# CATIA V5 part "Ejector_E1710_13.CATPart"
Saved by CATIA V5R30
Part number: Vyhazovac_4x160_1
Nomenclature: E1710/4x160
Description: MEUSBURGER
Property "Material": "1.221"
Publications: "__DrillHole", "Base"
Bounding box of the stored display mesh (mm): x -3.996 to 3.996, y -3.999 to 3.999, z 0 to 152
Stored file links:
  E:\Bakalarka\Model\Forma_v7\Ejector_E1710_13.CATPart
  E:\dev\MoldDesign\intel_a\startup\components\MoldCatalog\Ejector\Meusburger\Ejector_E1710\TableE1710.txt
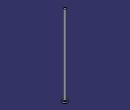
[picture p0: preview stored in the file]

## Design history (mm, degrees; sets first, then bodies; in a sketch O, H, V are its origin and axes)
Parameters
  Ref = "E1710/4x160" {design table}
  D1 = 4 mm {design table}
  D3 = 8 mm {design table}
  L = 160 mm {design table}
  L3 = 3 mm {design table}
  R = 0.3 mm {design table}
  k_d3 = 9 mm {design table}
  k_d1 = 4.2 mm {design table}
  k_F = 0.3 mm {design table}
  kl = 17 mm {design table}
  Mat = "1.221" {design table}
  HeatTreat = "ISO6751" {design table}
  Offset_Parting = 10 mm
  Anti_Rotation = "Normal"
  Anti_Rotation_D = 2.3 mm
  Anti_Rotation_D_Icut = 2.3 mm
  Add_Length_L = 0.8377 mm
  Add_Length_D3 = 0 mm
  SupplierRef = "Meusburger 2017"
  BmpRef = "F_MldEjectorD1"
  DrillHole_Length = 225 mm
  ValidationTest = false
  Anti_Rotation_D_min = 2.3 mm {= OffSet_D1 /2}
  Anti_Rotation_D_max = 3.925 mm {= D3/2-0.075mm}
  Anti_Rotation_D_ref = 2.3 mm {= Anti_Rotation_D}
  Anti_Rotation_D_Icut_ref = 2.3 mm {= Anti_Rotation_D_Icut}
  Anti_Rotation_Ref_Icut = 2.3246 mm
  Offset_L = 20 mm
  D = 4 mm {= D1}
  OffSet_D1 = 4.6 mm {= D1+2*R}
  OffSet_D3 = 9 mm {= D3+1mm}
  XG_Split = -159.5 mm
  YG_Split = 0 mm
  ZG_Split = -198 mm
  DirX_Split = 0 mm
  DirY_Split = 0 mm
  DirZ_Split = 1 mm
Set1 "BaseBody"
  Point1 "Base": (0, 0, 0)
  Plane1: type Offset, RefPlane xy-plane, Offset 225 {= DrillHole_Length}, reversed
  Sketch1 "Sketch.2" on xy-plane, origin (0, 0, 0), H (1, 0, 0), V (0, 1, 0)
    point P1 (-0.46, 1.1623)
    point P2 (0.46, 1.1623)
    construction line L1 (-0.46, 1.1623) -> (0.46, 1.1623)
    point P3 (0.46, -1.1623)
    line L2 (0.46, -1.1623) -> (0.46, 1.1623)
    point P4 (-0.46, -1.1623)
    construction line L3 (0.46, -1.1623) -> (-0.46, -1.1623)
    line L4 (-0.46, 1.1623) -> (-0.46, -1.1623)
    point P5 (-0.21, 1.1623)
    arc A1 centre (-0.21, 1.1623) radius 0.25 from (-0.21, 1.4123) to (-0.46, 1.1623) ccw
    point P7 (0.21, 1.1623)
    point P8 (0.21, 1.4123)
    arc A2 centre (0.21, 1.1623) radius 0.25 from (0.46, 1.1623) to (0.21, 1.4123) ccw
    line L5 (-0.21, 1.4123) -> (0.21, 1.4123)
    point P9 (-0.46, -1.1623)
    arc A3 centre (-0.21, -1.1623) radius 0.25 from (-0.46, -1.1623) to (-0.21, -1.4123) ccw
    point P11 (0.21, -1.4123)
    line L6 (-0.21, -1.4123) -> (0.21, -1.4123)
    point P12 (0.46, -1.1623)
    arc A4 centre (0.21, -1.1623) radius 0.25 from (0.21, -1.4123) to (0.46, -1.1623) ccw
    point P14 (-0.46, 1.1623)
    point P15 (-0.46, -1.1623)
    point P16 (0.46, 1.1623)
    point P17 (0.46, -1.1623)
    reference projected circle E1 centre (0, 0) radius 1.25 from edge [face of Shaft1 from Sketch2.L3 | face of Shaft1 from Sketch2.L4]
    reference projected circle E2 centre (0, 0) radius 1.25 from edge [face of Shaft1 from Sketch2.L3 | face of Shaft1 from Sketch2.L4]
    reference projected circle E3 centre (0, 0) radius 1.25 from edge [face of Shaft1 from Sketch2.L3 | face of Shaft1 from Sketch2.L4]
    reference projected circle E4 centre (0, 0) radius 1.25 from edge [face of Shaft1 from Sketch2.L3 | face of Shaft1 from Sketch2.L4]
    point P18 (-0.46, -1.1623)
    point P19 (-0.21, -1.4123)
    point P20 (0.21, -1.4123)
    point P21 (0.46, -1.1623)
    point P22 (-0.21, -1.4123)
    point P23 (0.21, -1.4123)
    distance P14 P15 = 2.3246 (reference)
    distance P16 P17 = 2.3246 (reference)
    distance L1 P14 = 0 (reference)
    radius A1 = 2
    distance L4 V = 2.31
    distance L2 V = 3.935
    distance L5 L6 = 8
    horizontal: L1 H, L3 H, L5 H
    vertical: L2 V, L4 V
    coincidence: P5 L1, P7 L1, P3 P12, P14 L4, P15 L4, P16 L2, P17 L2, P14 E1, P15 E2, P16 E3, P17 E4, P3 P21, P4 P18, P20 P23, P19 P22
    tangency: A1 L4, A2 L2, A2 L5, A1 L5
    symmetry: P1 P9 H, A1 A3 H, P8 P11 H, L5 L6 H, P2 P12 H, A2 A4 H
  DatumSurface1
Body1 "PartBody" (main body)
  Sketch2 "Sketch.1" on zx-plane, origin (0, 0, 0), H (-1, 0, 0), V (0, 0, 1)
    point P1 (0, 160)
    line L1 (2, 160) -> (0, 160)
    line L2 (2, 3) -> (2, 160)
    line L3 (4, 3) -> (2, 3)
    line L4 (4, 0) -> (4, 3)
    point P5 (0, 0)
    line L5 (0, 0) -> (4, 0)
    point P6 (0, 160)
    axis line L6 (0, 160) -> (0, 0)
    point P7 (0, 0)
    point P8 (2, 3)
    point P9 (2, 3)
    line L7 (0, 160) -> (0, 0)
    distance L5 L3 = 3 {= L3}
    distance L5 L1 = 160 {= L}
    distance L2 L6 = 2 {= D1 /2}
    distance L4 L6 = 4 {= D3 /2}
    coincidence: L6 P5, P1 L6, L5 H, L6 V, P7 O, P6 P1, P8 P9
    vertical: L2 V, L7 V
    horizontal: L1 H
  Shaft1 "Shaft.1": profile Sketch2, axis Sketch2.L6, angle 360
  Pocket1 "Pocket.1": profile Sketch1, direction (0, 0, 1), length 4, outer side, deactivated
  Pocket2 "Pocket.2": profile Sketch1, direction (0, 0, 1), length 4, outer side, deactivated
  Fillet1: radius 0.3 {= R}, on edge [face of Shaft1 from Sketch2.L2 | face of Shaft1 from Sketch2.L3]
  Pocket3: profile face of Shaft1 from Sketch2.L1, direction along face of Shaft1 from Sketch2.L1 reversed, up to face of DatumSurface1
Body2 "__DrillHole"
  Sketch3 "Sketch.3" on face of Shaft1, origin (0, 0, 0), H (1, 0, 0), V (0, -1, 0)
    point P1 (0, 0)
    reference projected point E1 (0, 0) from Point1
    coincidence: E1 P1
  Hole1 "Hole.1": placed by Sketch3, at (0, 0, 0) direction (0, 0, 1), diameter 4.6 {= OffSet_D1}, depth 140 {= L-Offset_L}
  Sketch4 "Sketch.4" on face of Shaft1, origin (0, 0, 0), H (1, 0, 0), V (0, -1, 0)
    point P1 (0, 0)
    reference projected point E1 (0, 0) from Point1
    coincidence: E1 P1
  Hole2 "Hole.2": placed by Sketch4, at (0, 0, 0) direction (0, 0, 1), diameter 4 {= D1}, depth 160 {= L}
  Sketch5 "Sketch.5" on face of Shaft1 from Sketch2.L3, origin (0, 0, 3), H (1, 0, 0), V (0, 1, 0)
    point P1 (0, 0)
    reference projected point E1 (0, 0) from Point1
    coincidence: E1 P1
  Hole3 "Hole.3": placed by Sketch5, at (0, 0, 3) direction (0, 0, -1), diameter 9 {= OffSet_D3}, depth 228 {= L3 +DrillHole_Length}
  Chamfer1: length 0.3 {= k_F}, angle 45, on edge [face of Hole1 | face of Hole3]
  Body3 "__Body.1"
    Pocket4 "Pocket.3": profile Sketch1, direction (0, 0, -1), length 225, opposite side length 3, deactivated
  Assemble1: tool Body3
  Chamfer2: length 0.3 {= k_F}, angle 45, on edge [start face of Pocket4 | face of Hole1], deactivated
  Body4 "__Body.2"
    Pocket5 "Pocket.4": profile Sketch1, direction (0, 0, -1), length 225, opposite side length 3, deactivated
  Assemble2: tool Body4
  Chamfer3: length 0.3 {= k_F}, angle 45, on edge [start face of Pocket5 | face of Hole1], deactivated
Relations
  design table "TableE1710", configuration 187, drives Ref, D1, D3, L, L3, R, k_d3, k_d1, k_F, kl, Mat, HeatTreat
  Offset_L = 20mm (deactivated)
  rule "Cut_Head_rule":
    let sketch_cut (length)
    let PartBody_Pocket_Sketch (Boolean)
    let I_PartBody_Pocket (Boolean)
    let D_PartBody_Pocket (Boolean)
    let N_DrillHole_Hole (Boolean)
    let N_DrillHole_Hole_Sketch (Boolean)
    let I_DrillHole_Pocket (Boolean)
    let D_DrillHole_Pocket (Boolean)
    /* --------------------------------------------------------------------------------------*/
    if Anti_Rotation =="Normal"
    {
    	sketch_cut=Anti_Rotation_D_max
    	PartBody_Pocket_Sketch = false
    	I_PartBody_Pocket = false
    	D_PartBody_Pocket = false
    	N_DrillHole_Hole = true
    	N_DrillHole_Hole_Sketch = true
    	I_DrillHole_Pocket = false
    	D_DrillHole_Pocket = false
    	Chamfer1.Activity= true
    	Chamfer2.Activity= false
    	Chamfer3.Activity= false
    }
    if Anti_Rotation == "I_Cut"
    {
    	sketch_cut=Anti_Rotation_D_Icut_ref
    	PartBody_Pocket_Sketch = true
    	I_PartBody_Pocket = true
    	D_PartBody_Pocket = false
    	N_DrillHole_Hole = false
    	N_DrillHole_Hole_Sketch = false
    	I_DrillHole_Pocket = true
    	D_DrillHole_Pocket = false
    	Chamfer1.Activity= false
    	Chamfer2.Activity= true
    	Chamfer3.Activity= false
    }
    if Anti_Rotation =="D_Cut"
    {
    	sketch_cut=Anti_Rotation_D_max
    	PartBody_Pocket_Sketch = true
    	I_PartBody_Pocket = false
    	D_PartBody_Pocket = true
    	N_DrillHole_Hole = false
    	N_DrillHole_Hole_Sketch = false
    	I_DrillHole_Pocket = false
    	D_DrillHole_Pocket = true
    	Chamfer1.Activity= false
    	Chamfer2.Activity= false
    	Chamfer3.Activity= true
    }
    /* --------------------------------------------------------------------------------------*/
    Sketch1.distance(L2 V) = sketch_cut+0.01mm
    Sketch1.distance(L4 V) =Anti_Rotation_D_ref+0.01mm
    Sketch1.radius(A1) =D/2
    Pocket4.FirstLimit.Depth = DrillHole_Length
    Pocket5.FirstLimit.Depth = DrillHole_Length
    Pocket1.FirstLimit.Depth = L3+1mm
    Pocket2.FirstLimit.Depth = L3+1mm
    Pocket4.SecondLimit.Depth = L3
    Pocket5.SecondLimit.Depth =L3
    Pocket1.Activity = I_PartBody_Pocket
    Pocket2.Activity = D_PartBody_Pocket
    Sketch1.Activity =PartBody_Pocket_Sketch
    Hole3.Activity= N_DrillHole_Hole
    Sketch5.Activity = N_DrillHole_Hole_Sketch
    Pocket4.Activity = I_DrillHole_Pocket
    Pocket5.Activity  = D_DrillHole_Pocket
  rule "Anti_Rotation_Icut_constrain":
    let Ref1(length)
    let Ref2(length)
    let Ref3(length)
    let Diam1(length)
    let Diam2(length)
    let Add_Length_Lmin (length)
    Ref1=Sketch1.distance(P14 P15)
    Ref2=Sketch1.distance(P16 P17)
    Diam1=D
    Diam2=D3
    /* --------------------------------------------------------------------*/
    if Ref1 >Ref2
    	Anti_Rotation_Ref_Icut = Ref1
    else
    	Anti_Rotation_Ref_Icut  =Ref2
    Add_Length_D3 .InferiorRange=Anti_Rotation_Ref_Icut /2+Diam1/2 -Diam2/2
    if Add_Length_D3 .InferiorRange<0mm
    	Add_Length_D3 .InferiorRange=0mm
    if ValidationTest == "true"
    	Ref3   = 2*Add_Length_L +Anti_Rotation_Ref_Icut  +2*Diam1/2
    else
    	Ref3  =Diam2+2*Add_Length_D3
    if Ref3 <Diam2
    {
    	Ref3 =Diam2
    }
    /* --------------------------------------------------------------------*/
    Sketch1.distance(L5 L6) = Ref3
    Add_Length_L .InferiorRange=Diam2/2-Anti_Rotation_Ref_Icut/2-Diam1/2
    Add_Length_Lmin=Diam2/2-Anti_Rotation_Ref_Icut/2-Diam1/2
    if Add_Length_Lmin<0mm
    	Add_Length_L .InferiorRange=0mm
    else
    	Add_Length_L .InferiorRange=Add_Length_Lmin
